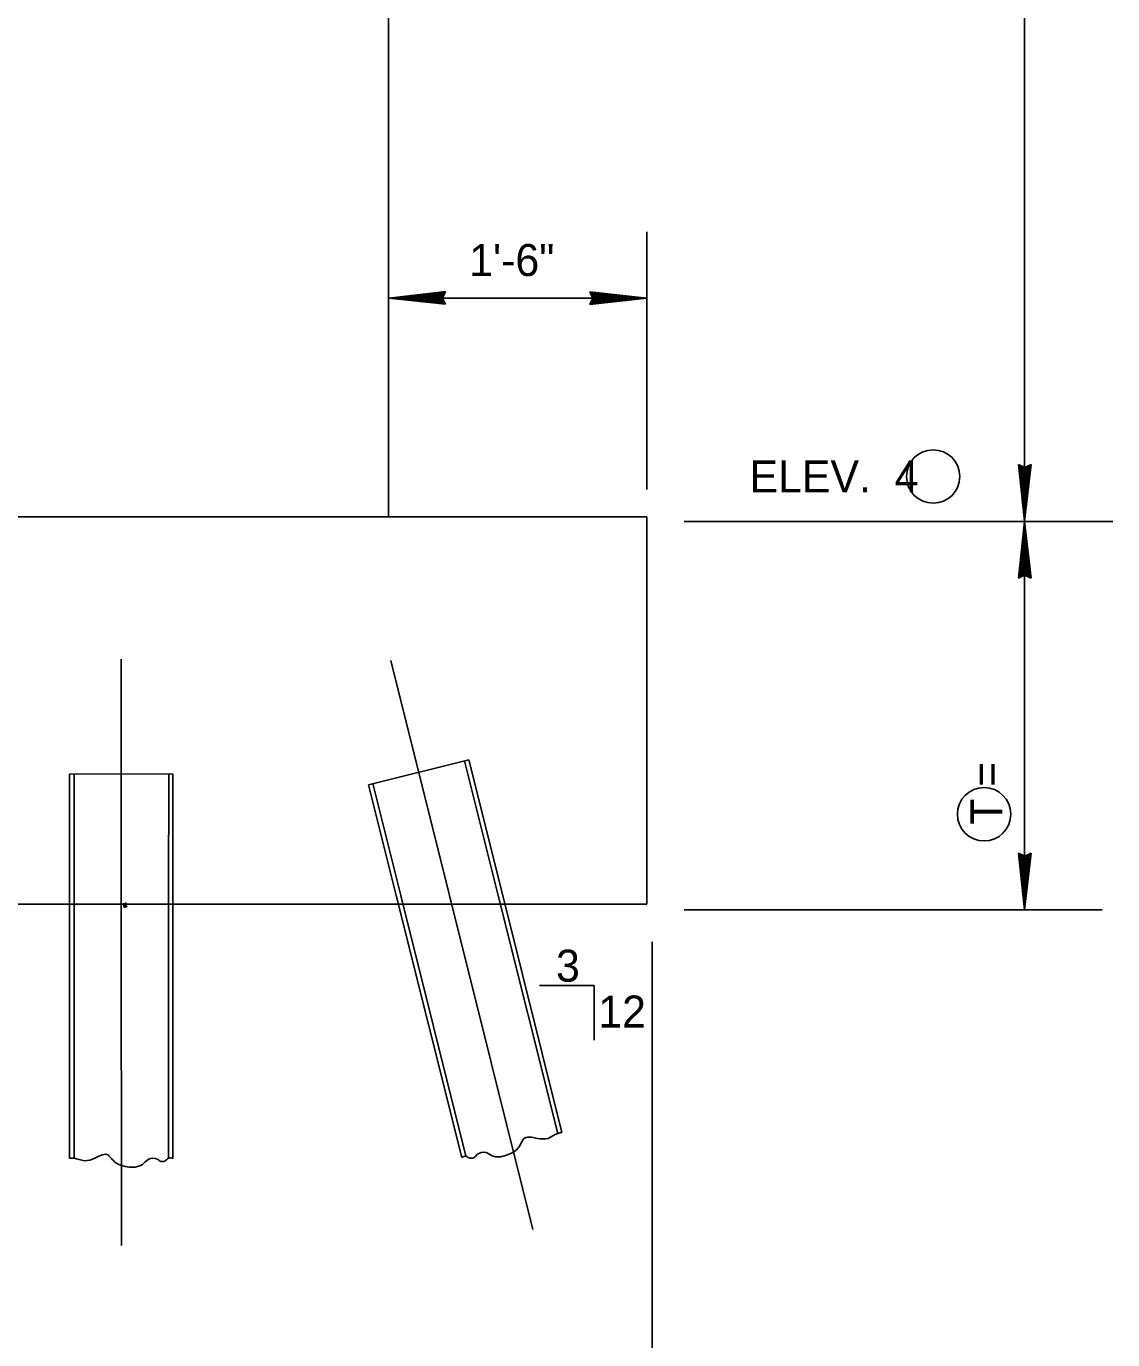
# Model space of a CAD drawing. Extents: x 1.6 to 6.29, y 2.8 to 7.08.
# Drawn here: x 3.374 to 3.798, y 4.967 to 5.479 of the extents above; entities that cross this region are included whole.
import ezdxf

# ---------------------------------------------------------------- set-up
doc = ezdxf.new("R2010")
doc.units = 0
doc.layers.add('Level 1', color=7, linetype='Continuous')
doc.layers.add('Level 5', color=7, linetype='Continuous')

msp = doc.modelspace()

# ---------------------------------------------------------------- linework, layer by layer
at = {"layer": 'Level 1'}
for p, q in [((3.51525, 5.792), (3.51525, 5.28792)), ((3.76367, 5.78783), (3.76367, 5.13442)), ((3.51525, 5.46592), (3.51525, 5.28792)), ((3.76367, 5.46592), (3.76367, 5.13442)), ((3.61608, 5.29858), (3.61608, 5.39917)), ((3.61608, 5.29858), (3.61608, 5.38192)), ((3.51542, 5.37333), (3.5375, 5.37583)), ((3.51542, 5.37333), (3.5375, 5.37583)), ((3.537, 5.37542), (3.52167, 5.37375)), ((3.537, 5.37542), (3.52167, 5.37375)), ((3.537, 5.37525), (3.52167, 5.37358)), ((3.537, 5.37525), (3.52167, 5.37358)), ((3.53708, 5.375), (3.52175, 5.37333)), ((3.53708, 5.375), (3.52175, 5.37333)), ((3.53708, 5.37475), (3.52175, 5.37308)), ((3.53708, 5.37475), (3.52175, 5.37308)), ((3.5375, 5.37583), (3.53633, 5.37333)), ((3.5375, 5.37583), (3.53633, 5.37333)), ((3.5365, 5.37433), (3.537, 5.37542)), ((3.5365, 5.37433), (3.537, 5.37542)), ((3.59383, 5.37575), (3.61608, 5.37333)), ((3.595, 5.37333), (3.59383, 5.37575)), ((3.59383, 5.37575), (3.61608, 5.37333)), ((3.595, 5.37333), (3.59383, 5.37575)), ((3.59425, 5.37542), (3.61083, 5.37358)), ((3.59425, 5.37542), (3.61083, 5.37358)), ((3.59425, 5.37533), (3.61083, 5.3735)), ((3.59425, 5.37533), (3.61083, 5.3735)), ((3.59425, 5.37525), (3.61083, 5.37342)), ((3.59425, 5.37525), (3.61083, 5.37342)), ((3.59425, 5.375), (3.61083, 5.37317)), ((3.59425, 5.375), (3.61083, 5.37317)), ((3.59433, 5.3755), (3.61083, 5.37367)), ((3.59433, 5.3755), (3.61083, 5.37367)), ((3.59542, 5.3735), (3.59442, 5.37508)), ((3.59442, 5.37508), (3.59492, 5.37475)), ((3.59542, 5.3735), (3.59442, 5.37508)), ((3.59442, 5.37508), (3.59492, 5.37475)), ((3.59967, 5.37425), (3.59483, 5.3745)), ((3.59483, 5.3745), (3.6025, 5.37392)), ((3.59967, 5.37425), (3.59483, 5.3745)), ((3.59483, 5.3745), (3.6025, 5.37392)), ((3.59492, 5.37475), (3.59542, 5.37392)), ((3.59492, 5.37475), (3.59542, 5.37392)), ((3.5955, 5.37483), (3.59517, 5.37325)), ((3.5955, 5.37483), (3.59517, 5.37325)), ((3.59592, 5.37417), (3.5955, 5.37483)), ((3.59592, 5.37417), (3.5955, 5.37483)), ((3.5375, 5.37333), (3.51542, 5.37333)), ((3.5375, 5.37092), (3.51542, 5.37333)), ((3.5375, 5.37333), (3.51542, 5.37333)), ((3.5375, 5.37092), (3.51542, 5.37333)), ((3.51642, 5.37333), (3.61558, 5.37333)), ((3.51642, 5.37333), (3.61558, 5.37333)), ((3.52108, 5.37375), (3.51842, 5.3735)), ((3.52108, 5.37375), (3.51842, 5.3735)), ((3.51842, 5.3735), (3.536, 5.37358)), ((3.51842, 5.3735), (3.536, 5.37358)), ((3.51908, 5.37317), (3.52108, 5.37375)), ((3.51908, 5.37317), (3.52108, 5.37375)), ((3.52892, 5.37275), (3.51908, 5.37317)), ((3.52892, 5.37275), (3.51908, 5.37317)), ((3.537, 5.37125), (3.52058, 5.37308)), ((3.537, 5.37133), (3.52058, 5.37308)), ((3.537, 5.37125), (3.52058, 5.37308)), ((3.537, 5.37133), (3.52058, 5.37308)), ((3.537, 5.37117), (3.52058, 5.373)), ((3.537, 5.37117), (3.52058, 5.373)), ((3.53708, 5.37167), (3.52067, 5.37342)), ((3.53708, 5.37167), (3.52067, 5.37342)), ((3.537, 5.37142), (3.52067, 5.37325)), ((3.537, 5.37142), (3.52067, 5.37325)), ((3.525, 5.37308), (3.53633, 5.37433)), ((3.525, 5.37308), (3.53633, 5.37433)), ((3.53625, 5.37392), (3.525, 5.37308)), ((3.53625, 5.37392), (3.525, 5.37308)), ((3.52617, 5.37292), (3.52617, 5.37317)), ((3.52617, 5.37317), (3.52808, 5.37308)), ((3.52617, 5.37292), (3.52617, 5.37317)), ((3.52617, 5.37317), (3.52808, 5.37308)), ((3.536, 5.37308), (3.52617, 5.37292)), ((3.536, 5.37308), (3.52617, 5.37292)), ((3.52808, 5.37308), (3.536, 5.37292)), ((3.52808, 5.37308), (3.536, 5.37292)), ((3.53642, 5.37217), (3.52892, 5.37275)), ((3.53642, 5.37217), (3.52892, 5.37275)), ((3.536, 5.37292), (3.52967, 5.37275)), ((3.536, 5.37292), (3.52967, 5.37275)), ((3.52967, 5.37275), (3.53625, 5.37258)), ((3.52967, 5.37275), (3.53625, 5.37258)), ((3.536, 5.37358), (3.53083, 5.37392)), ((3.53083, 5.37392), (3.53625, 5.37392)), ((3.536, 5.37358), (3.53083, 5.37392)), ((3.53083, 5.37392), (3.53625, 5.37392)), ((3.53625, 5.37258), (3.53158, 5.37242)), ((3.53625, 5.37258), (3.53158, 5.37242)), ((3.53158, 5.37242), (3.53642, 5.37217)), ((3.53158, 5.37242), (3.53642, 5.37217)), ((3.53592, 5.37275), (3.53533, 5.3725)), ((3.53592, 5.37275), (3.53533, 5.3725)), ((3.53533, 5.3725), (3.53575, 5.37183)), ((3.53533, 5.3725), (3.53575, 5.37183)), ((3.53575, 5.37183), (3.53608, 5.37342)), ((3.53575, 5.37183), (3.53608, 5.37342)), ((3.53633, 5.37433), (3.53592, 5.37308)), ((3.53633, 5.37433), (3.53592, 5.37308)), ((3.53592, 5.37308), (3.53683, 5.37158)), ((3.53592, 5.37308), (3.53683, 5.37158)), ((3.53633, 5.37192), (3.53592, 5.37275)), ((3.53633, 5.37192), (3.53592, 5.37275)), ((3.53608, 5.37342), (3.5365, 5.37433)), ((3.53608, 5.37342), (3.5365, 5.37433)), ((3.53633, 5.37333), (3.5375, 5.37092)), ((3.53633, 5.37333), (3.5375, 5.37092)), ((3.53683, 5.37158), (3.53633, 5.37192)), ((3.53683, 5.37158), (3.53633, 5.37192)), ((3.59383, 5.37333), (3.61608, 5.37333)), ((3.61608, 5.37333), (3.59383, 5.37083)), ((3.59383, 5.37083), (3.595, 5.37333)), ((3.59383, 5.37333), (3.61608, 5.37333)), ((3.61608, 5.37333), (3.59383, 5.37083)), ((3.59383, 5.37083), (3.595, 5.37333)), ((3.59417, 5.37192), (3.60967, 5.37358)), ((3.59417, 5.37192), (3.60967, 5.37358)), ((3.59425, 5.37167), (3.60967, 5.37333)), ((3.59425, 5.37167), (3.60967, 5.37333)), ((3.59425, 5.37142), (3.60975, 5.37308)), ((3.59425, 5.37142), (3.60975, 5.37308)), ((3.59433, 5.37117), (3.60975, 5.37292)), ((3.59433, 5.37117), (3.60975, 5.37292)), ((3.59475, 5.37233), (3.59433, 5.37125)), ((3.59475, 5.37233), (3.59433, 5.37125)), ((3.59517, 5.37325), (3.59475, 5.37233)), ((3.59517, 5.37325), (3.59475, 5.37233)), ((3.60633, 5.3735), (3.59492, 5.37233)), ((3.59492, 5.37233), (3.59542, 5.3735)), ((3.60633, 5.3735), (3.59492, 5.37233)), ((3.59492, 5.37233), (3.59542, 5.3735)), ((3.59508, 5.37408), (3.59967, 5.37425)), ((3.59508, 5.37408), (3.59967, 5.37425)), ((3.60175, 5.37392), (3.59508, 5.37408)), ((3.60175, 5.37392), (3.59508, 5.37408)), ((3.59508, 5.37275), (3.60633, 5.3735)), ((3.59508, 5.37275), (3.60633, 5.3735)), ((3.6005, 5.37275), (3.59508, 5.37275)), ((3.6005, 5.37275), (3.59508, 5.37275)), ((3.59533, 5.37375), (3.60175, 5.37392)), ((3.59533, 5.37375), (3.60175, 5.37392)), ((3.59533, 5.37358), (3.60525, 5.37375)), ((3.60333, 5.37358), (3.59533, 5.37375)), ((3.59533, 5.37358), (3.60525, 5.37375)), ((3.60333, 5.37358), (3.59533, 5.37375)), ((3.61308, 5.37317), (3.59533, 5.37308)), ((3.61308, 5.37317), (3.59533, 5.37308)), ((3.59533, 5.37308), (3.6005, 5.37275)), ((3.59533, 5.37308), (3.6005, 5.37275)), ((3.59542, 5.37392), (3.59592, 5.37417)), ((3.59542, 5.37392), (3.59592, 5.37417)), ((3.6025, 5.37392), (3.61233, 5.3735)), ((3.6025, 5.37392), (3.61233, 5.3735)), ((3.60517, 5.3735), (3.60333, 5.37358)), ((3.60517, 5.3735), (3.60333, 5.37358)), ((3.60525, 5.37375), (3.60517, 5.3735)), ((3.60525, 5.37375), (3.60517, 5.3735)), ((3.61233, 5.3735), (3.61033, 5.37292)), ((3.61233, 5.3735), (3.61033, 5.37292)), ((3.61033, 5.37292), (3.61308, 5.37317)), ((3.61033, 5.37292), (3.61308, 5.37317)), ((3.76367, 5.28625), (3.76125, 5.30833)), ((3.76125, 5.30833), (3.76375, 5.30717)), ((3.76367, 5.28625), (3.76125, 5.30833)), ((3.76125, 5.30833), (3.76375, 5.30717)), ((3.76158, 5.30792), (3.76333, 5.2925)), ((3.76158, 5.30792), (3.76333, 5.2925)), ((3.76267, 5.30742), (3.76167, 5.30792)), ((3.76267, 5.30742), (3.76167, 5.30792)), ((3.76183, 5.30792), (3.7635, 5.2925)), ((3.76183, 5.30792), (3.7635, 5.2925)), ((3.76208, 5.30792), (3.76375, 5.29258)), ((3.76208, 5.30792), (3.76375, 5.29258)), ((3.76233, 5.30792), (3.76408, 5.29267)), ((3.76233, 5.30792), (3.76408, 5.29267)), ((3.76367, 5.30833), (3.76367, 5.28625)), ((3.76617, 5.30833), (3.76367, 5.28625)), ((3.76367, 5.30833), (3.76367, 5.28625)), ((3.76617, 5.30833), (3.76367, 5.28625)), ((3.76542, 5.30792), (3.76367, 5.2915)), ((3.76542, 5.30792), (3.76367, 5.2915)), ((3.76375, 5.30717), (3.76617, 5.30833)), ((3.76375, 5.30717), (3.76617, 5.30833)), ((3.76558, 5.30792), (3.76375, 5.2915)), ((3.76558, 5.30792), (3.76375, 5.2915)), ((3.76575, 5.30792), (3.764, 5.29142)), ((3.76575, 5.30792), (3.764, 5.29142)), ((3.764, 5.30675), (3.7655, 5.30775)), ((3.764, 5.30675), (3.7655, 5.30775)), ((3.76592, 5.30792), (3.76408, 5.29142)), ((3.76583, 5.30792), (3.76408, 5.29142)), ((3.76592, 5.30792), (3.76408, 5.29142)), ((3.76583, 5.30792), (3.76408, 5.29142)), ((3.7655, 5.30775), (3.76517, 5.30725)), ((3.7655, 5.30775), (3.76517, 5.30725)), ((3.76367, 5.30692), (3.76267, 5.30742)), ((3.76367, 5.30692), (3.76267, 5.30742)), ((3.764, 5.29583), (3.76267, 5.30725)), ((3.76267, 5.30725), (3.764, 5.30675)), ((3.764, 5.29583), (3.76267, 5.30725)), ((3.76267, 5.30725), (3.764, 5.30675)), ((3.76317, 5.30175), (3.76317, 5.30717)), ((3.76317, 5.30717), (3.764, 5.29583)), ((3.76317, 5.30175), (3.76317, 5.30717)), ((3.76317, 5.30717), (3.764, 5.29583)), ((3.7635, 5.30683), (3.76317, 5.30175)), ((3.7635, 5.30683), (3.76317, 5.30175)), ((3.76358, 5.28925), (3.7635, 5.30683)), ((3.76358, 5.28925), (3.7635, 5.30683)), ((3.76525, 5.30658), (3.76367, 5.30692)), ((3.76525, 5.30658), (3.76367, 5.30692)), ((3.76408, 5.30683), (3.76408, 5.297)), ((3.76408, 5.29892), (3.76408, 5.30683)), ((3.76408, 5.30683), (3.76442, 5.3005)), ((3.76408, 5.30683), (3.76408, 5.297)), ((3.76408, 5.29892), (3.76408, 5.30683)), ((3.76408, 5.30683), (3.76442, 5.3005)), ((3.76483, 5.30733), (3.76433, 5.29975)), ((3.76483, 5.30733), (3.76433, 5.29975)), ((3.76517, 5.30725), (3.76433, 5.30675)), ((3.76517, 5.30725), (3.76433, 5.30675)), ((3.76433, 5.30675), (3.7645, 5.30625)), ((3.76433, 5.30675), (3.7645, 5.30625)), ((3.76442, 5.3005), (3.76442, 5.30717)), ((3.76442, 5.30717), (3.76458, 5.3025)), ((3.76442, 5.3005), (3.76442, 5.30717)), ((3.76442, 5.30717), (3.76458, 5.3025)), ((3.7645, 5.30625), (3.76525, 5.30658)), ((3.7645, 5.30625), (3.76525, 5.30658)), ((3.76458, 5.3025), (3.76483, 5.30733)), ((3.76458, 5.3025), (3.76483, 5.30733)), ((3.76433, 5.29975), (3.76383, 5.28992)), ((3.76433, 5.29975), (3.76383, 5.28992)), ((3.76383, 5.29708), (3.76408, 5.29892)), ((3.76383, 5.29708), (3.76408, 5.29892)), ((3.76408, 5.297), (3.76383, 5.29708)), ((3.76408, 5.297), (3.76383, 5.29708)), ((3.2215, 5.28792), (3.51525, 5.28792)), ((3.2215, 5.28792), (3.51525, 5.28792)), ((3.51525, 5.28792), (3.61608, 5.28792)), ((3.51525, 5.28792), (3.61608, 5.28792)), ((3.61608, 5.28792), (3.61608, 5.13667)), ((3.61608, 5.28792), (3.61608, 5.13667)), ((3.76383, 5.28992), (3.76333, 5.292)), ((3.76333, 5.292), (3.76358, 5.28925)), ((3.76383, 5.28992), (3.76333, 5.292)), ((3.76333, 5.292), (3.76358, 5.28925)), ((3.63067, 5.28608), (3.79808, 5.28608)), ((3.63067, 5.28608), (3.79808, 5.28608)), ((3.76125, 5.264), (3.76367, 5.28608)), ((3.76125, 5.264), (3.76367, 5.28608)), ((3.76308, 5.27258), (3.76358, 5.28242)), ((3.76308, 5.27258), (3.76358, 5.28242)), ((3.76358, 5.28242), (3.76408, 5.28033)), ((3.76358, 5.28242), (3.76408, 5.28033)), ((3.76367, 5.28608), (3.76617, 5.264)), ((3.76367, 5.28608), (3.76617, 5.264)), ((3.76408, 5.28033), (3.76383, 5.28308)), ((3.76383, 5.28308), (3.76392, 5.2655)), ((3.76408, 5.28033), (3.76383, 5.28308)), ((3.76383, 5.28308), (3.76392, 5.2655)), ((3.76158, 5.2645), (3.76333, 5.28092)), ((3.76158, 5.26442), (3.76342, 5.28092)), ((3.76158, 5.2645), (3.76333, 5.28092)), ((3.76158, 5.26442), (3.76342, 5.28092)), ((3.76167, 5.26442), (3.7635, 5.28092)), ((3.76167, 5.26442), (3.7635, 5.28092)), ((3.76183, 5.26442), (3.76358, 5.28083)), ((3.76183, 5.26442), (3.76358, 5.28083)), ((3.762, 5.26442), (3.76383, 5.28083)), ((3.762, 5.26442), (3.76383, 5.28083)), ((3.76508, 5.26433), (3.76342, 5.27967)), ((3.76508, 5.26433), (3.76342, 5.27967)), ((3.76533, 5.26442), (3.76367, 5.27975)), ((3.76533, 5.26442), (3.76367, 5.27975)), ((3.76558, 5.26442), (3.76392, 5.27983)), ((3.76558, 5.26442), (3.76392, 5.27983)), ((3.76583, 5.2645), (3.76408, 5.27983)), ((3.76583, 5.2645), (3.76408, 5.27983)), ((3.76258, 5.265), (3.76308, 5.27258)), ((3.76258, 5.265), (3.76308, 5.27258)), ((3.76308, 5.27183), (3.76292, 5.26525)), ((3.76308, 5.27183), (3.76292, 5.26525)), ((3.76325, 5.2655), (3.76308, 5.27183)), ((3.76325, 5.2655), (3.76308, 5.27183)), ((3.76342, 5.2655), (3.76325, 5.27533)), ((3.76325, 5.27533), (3.76358, 5.27525)), ((3.76342, 5.2655), (3.76325, 5.27533)), ((3.76325, 5.27533), (3.76358, 5.27525)), ((3.76342, 5.27342), (3.76325, 5.2655)), ((3.76342, 5.27342), (3.76325, 5.2655)), ((3.76358, 5.27525), (3.76342, 5.27342)), ((3.76358, 5.27525), (3.76342, 5.27342)), ((3.76425, 5.26525), (3.7635, 5.2765)), ((3.7635, 5.2765), (3.76467, 5.26508)), ((3.76425, 5.26525), (3.7635, 5.2765)), ((3.7635, 5.2765), (3.76467, 5.26508)), ((3.76283, 5.26983), (3.76258, 5.265)), ((3.76283, 5.26983), (3.76258, 5.265)), ((3.76292, 5.26525), (3.76283, 5.26983)), ((3.76292, 5.26525), (3.76283, 5.26983)), ((3.76392, 5.2655), (3.76425, 5.27067)), ((3.76392, 5.2655), (3.76425, 5.27067)), ((3.76425, 5.27067), (3.76425, 5.26525)), ((3.76425, 5.27067), (3.76425, 5.26525)), ((3.76367, 5.26517), (3.76125, 5.264)), ((3.76367, 5.26517), (3.76125, 5.264)), ((3.7635, 5.26558), (3.76192, 5.26458)), ((3.7635, 5.26558), (3.76192, 5.26458)), ((3.76192, 5.26458), (3.76225, 5.26508)), ((3.76192, 5.26458), (3.76225, 5.26508)), ((3.76292, 5.26608), (3.76217, 5.26575)), ((3.76292, 5.26608), (3.76217, 5.26575)), ((3.76217, 5.26575), (3.76375, 5.26542)), ((3.76217, 5.26575), (3.76375, 5.26542)), ((3.76225, 5.26508), (3.76308, 5.26558)), ((3.76225, 5.26508), (3.76308, 5.26558)), ((3.76308, 5.26558), (3.76292, 5.26608)), ((3.76308, 5.26558), (3.76292, 5.26608)), ((3.76467, 5.26508), (3.7635, 5.26558)), ((3.76467, 5.26508), (3.7635, 5.26558)), ((3.76617, 5.264), (3.76367, 5.26517)), ((3.76617, 5.264), (3.76367, 5.26517)), ((3.76375, 5.26542), (3.76467, 5.265)), ((3.76375, 5.26542), (3.76467, 5.265)), ((3.76467, 5.265), (3.76575, 5.2645)), ((3.76467, 5.265), (3.76575, 5.2645)), ((3.76367, 5.1345), (3.76125, 5.15658)), ((3.76125, 5.15658), (3.76375, 5.15542)), ((3.76367, 5.1345), (3.76125, 5.15658)), ((3.76125, 5.15658), (3.76375, 5.15542)), ((3.76158, 5.15617), (3.76333, 5.14075)), ((3.76158, 5.15617), (3.76333, 5.14075)), ((3.76267, 5.15567), (3.76167, 5.15617)), ((3.76267, 5.15567), (3.76167, 5.15617)), ((3.76183, 5.15617), (3.7635, 5.14075)), ((3.76183, 5.15617), (3.7635, 5.14075)), ((3.76208, 5.15617), (3.76375, 5.14083)), ((3.76208, 5.15617), (3.76375, 5.14083)), ((3.76233, 5.15617), (3.76408, 5.14092)), ((3.76233, 5.15617), (3.76408, 5.14092)), ((3.76367, 5.15517), (3.76267, 5.15567)), ((3.76367, 5.15517), (3.76267, 5.15567)), ((3.764, 5.14408), (3.76267, 5.1555)), ((3.76267, 5.1555), (3.764, 5.155)), ((3.764, 5.14408), (3.76267, 5.1555)), ((3.76267, 5.1555), (3.764, 5.155)), ((3.76317, 5.15), (3.76317, 5.15542)), ((3.76317, 5.15542), (3.764, 5.14408)), ((3.76317, 5.15), (3.76317, 5.15542)), ((3.76317, 5.15542), (3.764, 5.14408)), ((3.7635, 5.15508), (3.76317, 5.15)), ((3.7635, 5.15508), (3.76317, 5.15)), ((3.76358, 5.1375), (3.7635, 5.15508)), ((3.76358, 5.1375), (3.7635, 5.15508)), ((3.76367, 5.15658), (3.76367, 5.1345)), ((3.76617, 5.15658), (3.76367, 5.1345)), ((3.76367, 5.15658), (3.76367, 5.1345)), ((3.76617, 5.15658), (3.76367, 5.1345)), ((3.76542, 5.15617), (3.76367, 5.13975)), ((3.76542, 5.15617), (3.76367, 5.13975)), ((3.76525, 5.15483), (3.76367, 5.15517)), ((3.76525, 5.15483), (3.76367, 5.15517)), ((3.76375, 5.15542), (3.76617, 5.15658)), ((3.76375, 5.15542), (3.76617, 5.15658)), ((3.76558, 5.15617), (3.76375, 5.13975)), ((3.76558, 5.15617), (3.76375, 5.13975)), ((3.76575, 5.15617), (3.764, 5.13967)), ((3.76575, 5.15617), (3.764, 5.13967)), ((3.764, 5.155), (3.7655, 5.156)), ((3.764, 5.155), (3.7655, 5.156)), ((3.76592, 5.15617), (3.76408, 5.13967)), ((3.76583, 5.15617), (3.76408, 5.13967)), ((3.76592, 5.15617), (3.76408, 5.13967)), ((3.76583, 5.15617), (3.76408, 5.13967)), ((3.76408, 5.15508), (3.76408, 5.14525)), ((3.76408, 5.14717), (3.76408, 5.15508)), ((3.76408, 5.15508), (3.76442, 5.14875)), ((3.76408, 5.15508), (3.76408, 5.14525)), ((3.76408, 5.14717), (3.76408, 5.15508)), ((3.76408, 5.15508), (3.76442, 5.14875)), ((3.76483, 5.15558), (3.76433, 5.148)), ((3.76483, 5.15558), (3.76433, 5.148)), ((3.76517, 5.1555), (3.76433, 5.155)), ((3.76517, 5.1555), (3.76433, 5.155)), ((3.76433, 5.155), (3.7645, 5.1545)), ((3.76433, 5.155), (3.7645, 5.1545)), ((3.76442, 5.14875), (3.76442, 5.15542)), ((3.76442, 5.15542), (3.76458, 5.15075)), ((3.76442, 5.14875), (3.76442, 5.15542)), ((3.76442, 5.15542), (3.76458, 5.15075)), ((3.7645, 5.1545), (3.76525, 5.15483)), ((3.7645, 5.1545), (3.76525, 5.15483)), ((3.76458, 5.15075), (3.76483, 5.15558)), ((3.76458, 5.15075), (3.76483, 5.15558)), ((3.7655, 5.156), (3.76517, 5.1555)), ((3.7655, 5.156), (3.76517, 5.1555)), ((3.76433, 5.148), (3.76383, 5.13817)), ((3.76433, 5.148), (3.76383, 5.13817)), ((3.76383, 5.14533), (3.76408, 5.14717)), ((3.76383, 5.14533), (3.76408, 5.14717)), ((3.76408, 5.14525), (3.76383, 5.14533)), ((3.76408, 5.14525), (3.76383, 5.14533)), ((3.76383, 5.13817), (3.76333, 5.14025)), ((3.76333, 5.14025), (3.76358, 5.1375)), ((3.76383, 5.13817), (3.76333, 5.14025)), ((3.76333, 5.14025), (3.76358, 5.1375)), ((3.61608, 5.13667), (3.22175, 5.13667)), ((3.61608, 5.13667), (3.22175, 5.13667)), ((3.63067, 5.13442), (3.79392, 5.13442)), ((3.63067, 5.13442), (3.79392, 5.13442)), ((3.61817, 5.122), (3.61817, 4.97467)), ((3.61817, 5.122), (3.61817, 4.9115))]:
    msp.add_line(p, q, dxfattribs=at)
for centre in [(3.72796, 5.30365), (3.72796, 5.30365), (3.74785, 5.17179)]:
    msp.add_circle(centre, 0.01042, dxfattribs=at)
at = {"layer": 'Level 5'}
for p, q in [((3.41083, 5.23233), (3.41083, 5.14)), ((3.51617, 5.23175), (3.53908, 5.14)), ((3.54667, 5.19308), (3.50742, 5.18333)), ((3.54492, 5.19267), (3.55808, 5.14)), ((3.54667, 5.19308), (3.55992, 5.14)), ((3.39067, 5.18742), (3.43108, 5.1875)), ((3.39067, 5.18742), (3.39067, 5.14)), ((3.3925, 5.1875), (3.39242, 5.14)), ((3.42942, 5.1875), (3.42933, 5.14)), ((3.43108, 5.1875), (3.43108, 5.14)), ((3.50742, 5.18333), (3.51825, 5.14)), ((3.50908, 5.18375), (3.52, 5.14)), ((3.39067, 5.14), (3.39067, 5.0375)), ((3.39242, 5.14), (3.39242, 5.0375)), ((3.41083, 5.14), (3.41092, 5.00342)), ((3.42933, 5.14), (3.42933, 5.0375)), ((3.43108, 5.14), (3.43108, 5.03742)), ((3.51825, 5.14), (3.54383, 5.03775)), ((3.52, 5.14), (3.5455, 5.03825)), ((3.53908, 5.14), (3.57167, 5.00967)), ((3.55808, 5.14), (3.58133, 5.04717)), ((3.55992, 5.14), (3.583, 5.04758)), ((3.57417, 5.10492), (3.5955, 5.10492)), ((3.5955, 5.10492), (3.5955, 5.08358))]:
    msp.add_line(p, q, dxfattribs=at)
for points in [[(3.583, 5.04758), (3.58133, 5.04717), (3.57758, 5.04525), (3.57342, 5.04525), (3.57108, 5.04567), (3.56825, 5.04525), (3.56783, 5.04475), (3.56683, 5.04292), (3.56592, 5.0415), (3.56267, 5.03917), (3.55992, 5.03825), (3.55617, 5.03825), (3.55342, 5.03967), (3.54967, 5.03875), (3.54875, 5.03775), (3.54642, 5.03775), (3.5455, 5.03825), (3.54383, 5.03775)], [(3.39067, 5.0375), (3.39242, 5.0375), (3.3965, 5.0365), (3.40058, 5.0375), (3.40275, 5.0385), (3.40558, 5.03883), (3.40608, 5.03842), (3.4075, 5.03683), (3.40875, 5.03575), (3.4125, 5.03425), (3.41533, 5.034), (3.419, 5.03492), (3.42133, 5.037), (3.42517, 5.037), (3.42633, 5.03625), (3.42858, 5.03683), (3.42933, 5.0375), (3.43108, 5.03742)]]:
    msp.add_spline(points, degree=3, dxfattribs=at)

# ---------------------------------------------------------------- texts
at = {"layer": 'Level 1'}
msp.add_text('1\'-6"', height=0.0125, dxfattribs=at).set_placement((3.54675, 5.38192))
msp.add_text('1\'-6"', height=0.0125, dxfattribs=at).set_placement((3.54675, 5.38192))
at = {"layer": 'Level 5'}
for s, p in [('ELEV.  4', (3.65625, 5.29742)), ('ELEV.  4', (3.65625, 5.29742)), ('3', (3.58067, 5.10642)), ('12', (3.59717, 5.0885))]:
    msp.add_text(s, height=0.0125, dxfattribs=at).set_placement(p)
for s, rotation, p in [('T =      ', 90, (3.755, 5.16767)), ('.', 14.0362, (3.41033, 5.13475))]:
    msp.add_text(s, height=0.0125, rotation=rotation, dxfattribs=at).set_placement(p)

doc.saveas('drawing.dxf')
